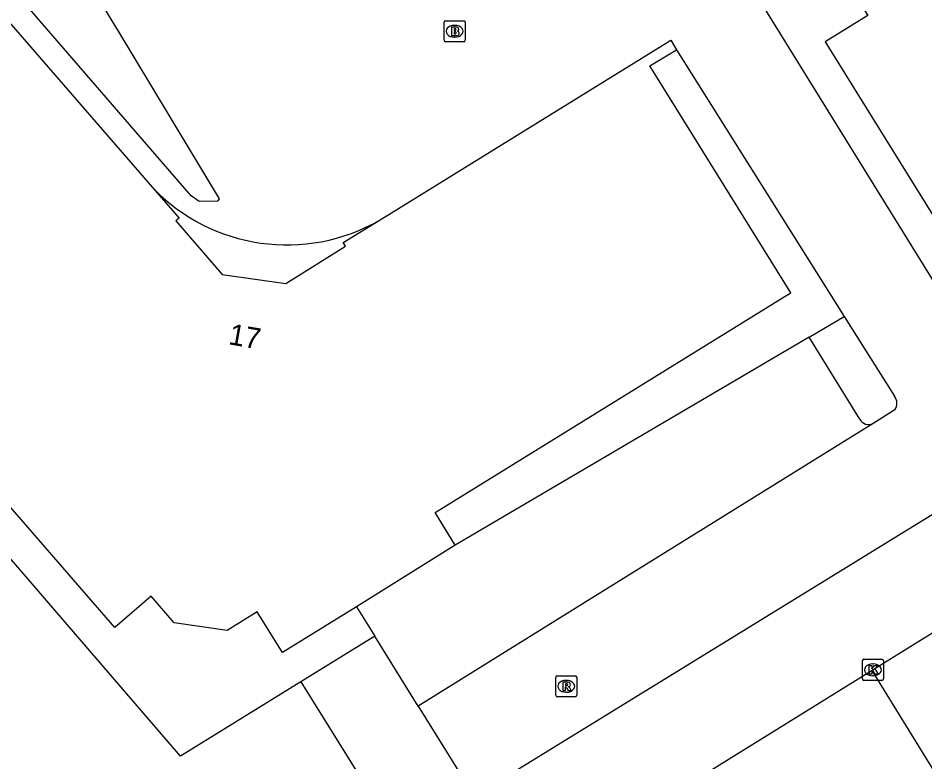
# Model space of a CAD drawing. Extents: x 160304 to 160954, y 383686 to 384161.
# Drawn here: x 160674.85 to 160717.85, y 384030.21 to 384065.5 of the extents above; entities that cross this region are included whole.
import ezdxf

# ---------------------------------------------------------------- set-up
doc = ezdxf.new("R2010")
doc.units = 0
for name, color, linetype in [('IMGEO_Brandkraan', 7, 'Continuous'), ('IMGEO_Kolk', 7, 'Continuous'), ('IMGEO_Pand', 7, 'Continuous'), ('IMGEO_Pand_nummerreeks', 7, 'Continuous'), ('IMGEO_Parkeervlak_open', 7, 'Continuous'), ('IMGEO_Rijbaan_lokaal_open', 7, 'Continuous'), ('IMGEO_Rioolput', 7, 'Continuous'), ('IMGEO_Voetpad_open', 7, 'Continuous')]:
    doc.layers.add(name, color=color, linetype=linetype)

msp = doc.modelspace()

# ---------------------------------------------------------------- linework, layer by layer
at = {"layer": 'IMGEO_Brandkraan'}
for p, q in [((160695.05, 384064.448), (160695.05, 384065.3)), ((160695.125, 384065.374), (160695.977, 384065.374)), ((160696.051, 384065.3), (160696.051, 384064.448)), ((160695.538, 384065.154), (160695.563, 384065.154)), ((160695.561, 384064.594), (160695.536, 384064.594)), ((160695.977, 384064.374), (160695.125, 384064.374))]:
    msp.add_line(p, q, dxfattribs=at)
for points in [[(160695.05, 384064.448), (160695.05, 384065.3)], [(160695.125, 384065.374), (160695.977, 384065.374)], [(160696.051, 384065.3), (160696.051, 384064.448)], [(160695.398, 384065.074), (160695.398, 384064.674), (160695.611, 384064.674)], [(160695.629, 384065.074), (160695.398, 384065.074)], [(160695.577, 384064.993), (160695.523, 384064.993), (160695.523, 384064.917)], [(160695.523, 384064.917), (160695.576, 384064.917)], [(160695.585, 384064.841), (160695.523, 384064.841), (160695.523, 384064.76)], [(160695.523, 384064.76), (160695.585, 384064.76)], [(160695.977, 384064.374), (160695.125, 384064.374)]]:
    msp.add_lwpolyline(points, dxfattribs=at)
for centre, radius, start, end in [((160695.127, 384065.298), 0.0765, 91.552, 178.448), ((160695.127, 384065.298), 0.0765, 91.552, 178.448), ((160695.975, 384065.298), 0.0765, 1.552, 88.448), ((160695.975, 384065.298), 0.0765, 1.552, 88.448), ((160695.578, 384064.955), 0.0379, 267.8285, 90.9355), ((160695.633, 384064.929), 0.145, 59.4692, 91.5367), ((160695.658, 384064.976), 0.0922, 285.5137, 58.1501), ((160695.663, 384064.784), 0.105, 301.3115, 78.989), ((160695.127, 384064.45), 0.0765, 181.552, 268.448), ((160695.127, 384064.45), 0.0765, 181.552, 268.448), ((160695.586, 384064.8), 0.0404, 269.8759, 90.5077), ((160695.617, 384064.925), 0.251, 268.6676, 293.5347), ((160695.975, 384064.45), 0.0765, 271.552, 358.448), ((160695.975, 384064.45), 0.0765, 271.552, 358.448)]:
    msp.add_arc(centre, radius, start, end, dxfattribs=at)
for centre, major_axis, ratio, start_param, end_param in [((160695.537, 384064.874), (-0.387, 0.002), 0.722429, 4.712389, 7.853982), ((160695.562, 384064.874), (-0.39, 0.002), 0.717154, 1.570796, 4.712389)]:
    msp.add_ellipse(centre, major_axis=major_axis, ratio=ratio, start_param=start_param, end_param=end_param, dxfattribs=at)
at = {"layer": 'IMGEO_Kolk'}
for p, q in [((160714.884, 384034.152), (160714.884, 384035.004)), ((160714.959, 384035.078), (160715.811, 384035.078)), ((160715.372, 384034.858), (160715.397, 384034.858)), ((160715.885, 384035.004), (160715.885, 384034.152)), ((160715.811, 384034.078), (160714.959, 384034.078)), ((160715.395, 384034.298), (160715.37, 384034.298))]:
    msp.add_line(p, q, dxfattribs=at)
for points in [[(160714.884, 384034.152), (160714.884, 384035.004)], [(160714.959, 384035.078), (160715.811, 384035.078)], [(160715.205, 384034.778), (160715.328, 384034.778), (160715.328, 384034.627), (160715.458, 384034.778), (160715.622, 384034.778), (160715.476, 384034.627), (160715.629, 384034.378), (160715.477, 384034.378), (160715.392, 384034.542), (160715.328, 384034.475), (160715.328, 384034.378), (160715.205, 384034.378), (160715.205, 384034.778)], [(160715.885, 384035.004), (160715.885, 384034.152)], [(160715.811, 384034.078), (160714.959, 384034.078)]]:
    msp.add_lwpolyline(points, dxfattribs=at)
for centre, start, end in [((160714.961, 384035.002), 91.552, 178.448), ((160714.961, 384035.002), 91.552, 178.448), ((160715.809, 384035.002), 1.552, 88.448), ((160715.809, 384035.002), 1.552, 88.448), ((160714.961, 384034.154), 181.552, 268.448), ((160714.961, 384034.154), 181.552, 268.448), ((160715.809, 384034.154), 271.552, 358.448), ((160715.809, 384034.154), 271.552, 358.448)]:
    msp.add_arc(centre, 0.0765, start, end, dxfattribs=at)
for centre, major_axis, ratio, start_param, end_param in [((160715.371, 384034.578), (-0.387, 0.002), 0.722429, 4.712389, 7.853982), ((160715.396, 384034.578), (-0.39, 0.002), 0.717154, 1.570796, 4.712389)]:
    msp.add_ellipse(centre, major_axis=major_axis, ratio=ratio, start_param=start_param, end_param=end_param, dxfattribs=at)
at = {"layer": 'IMGEO_Pand'}
for points in [[(160660.687, 384076.023), (160662.817, 384077.869), (160661.847, 384078.987), (160662.262, 384079.347), (160681.221, 384057.468)], [(160718.989, 384072.622), (160720.124, 384070.796), (160714.211, 384067.125), (160715.145, 384065.622), (160713.123, 384064.367), (160726.004, 384043.621), (160733.056, 384047.999)], [(160690.89, 384037.575), (160687.392, 384035.398), (160686.188, 384037.334), (160684.762, 384036.447), (160682.256, 384036.811), (160681.157, 384038.082), (160679.439, 384036.595), (160651.874, 384068.387)], [(160692.014, 384055.93), (160705.803, 384064.45), (160706.073, 384064.001)], [(160695.582, 384040.495), (160694.629, 384042.042), (160711.18, 384052.269), (160711.492, 384052.462), (160704.809, 384063.238), (160706.073, 384064.001)], [(160681.221, 384057.468), (160682.482, 384056.013), (160682.324, 384055.876), (160684.524, 384053.338), (160687.54, 384052.902), (160690.381, 384054.674), (160690.27, 384054.852), (160692.014, 384055.93)], [(160695.582, 384040.495), (160690.89, 384037.575)]]:
    msp.add_lwpolyline(points, dxfattribs=at)
at = {"layer": 'IMGEO_Parkeervlak_open'}
for points in [[(160693.825, 384032.859), (160691.762, 384036.175)], [(160715.343, 384034.554), (160706.863, 384029.281)]]:
    msp.add_lwpolyline(points, dxfattribs=at)
at = {"layer": 'IMGEO_Rijbaan_lokaal_open'}
for points in [[(160673.275, 384075.21), (160679.603, 384064.881), (160684.384, 384056.924), (160684.307, 384056.808), (160683.435, 384056.801), (160683.051, 384057.063), (160670.643, 384071.435), (160662.613, 384081.053), (160661.415, 384079.839), (160660.141, 384080.752), (160660.534, 384084.173), (160660.963, 384085.478)], [(160723.208, 384045.029), (160706.486, 384072.081), (160707.989, 384073.011)], [(160706.073, 384064.001), (160714.021, 384051.35)], [(160714.021, 384051.35), (160716.402, 384047.56)], [(160716.431, 384046.914), (160715.395, 384046.269)], [(160715.395, 384046.269), (160701.722, 384037.769), (160693.825, 384032.859)], [(160696.482, 384028.586), (160701.692, 384031.792), (160723.208, 384045.029)], [(160688.256, 384034.009), (160682.556, 384030.486), (160672.68, 384041.948)], [(160720.51, 384037.766), (160715.343, 384034.554)], [(160724.118, 384020.31), (160715.343, 384034.554)], [(160688.256, 384034.009), (160692.299, 384027.507)], [(160693.825, 384032.859), (160695.799, 384029.684)]]:
    msp.add_lwpolyline(points, dxfattribs=at)
for centre, radius, start, end in [((160687.592, 384063.537), 8.799, 223.6096, 300.1703), ((160715.974, 384047.217), 0.548, 326.4399, 38.7009)]:
    msp.add_arc(centre, radius, start, end, dxfattribs=at)
at = {"layer": 'IMGEO_Rioolput'}
for p, q in [((160700.342, 384033.372), (160700.342, 384034.224)), ((160700.417, 384034.298), (160701.269, 384034.298)), ((160700.83, 384034.078), (160700.855, 384034.078)), ((160701.343, 384034.224), (160701.343, 384033.372)), ((160700.853, 384033.518), (160700.828, 384033.518)), ((160701.269, 384033.298), (160700.417, 384033.298))]:
    msp.add_line(p, q, dxfattribs=at)
for points in [[(160700.342, 384033.372), (160700.342, 384034.224)], [(160700.417, 384034.298), (160701.269, 384034.298)], [(160700.931, 384033.996), (160700.679, 384033.998), (160700.679, 384033.598)], [(160700.857, 384033.917), (160700.803, 384033.917), (160700.803, 384033.836)], [(160701.343, 384034.224), (160701.343, 384033.372)], [(160700.679, 384033.598), (160700.803, 384033.598), (160700.803, 384033.76), (160700.814, 384033.76)], [(160700.803, 384033.836), (160700.855, 384033.836)], [(160700.861, 384033.731), (160700.932, 384033.598), (160701.072, 384033.598), (160701.007, 384033.724)], [(160701.269, 384033.298), (160700.417, 384033.298)]]:
    msp.add_lwpolyline(points, dxfattribs=at)
for centre, radius, start, end in [((160700.419, 384034.222), 0.0765, 91.552, 178.448), ((160700.419, 384034.222), 0.0765, 91.552, 178.448), ((160700.863, 384033.821), 0.0964, 77.0061, 93.1865), ((160700.877, 384033.878), 0.0378, 276.6634, 79.6772), ((160700.93, 384033.886), 0.109, 350.3612, 89.416), ((160701.267, 384034.222), 0.0765, 1.552, 88.448), ((160701.267, 384034.222), 0.0765, 1.552, 88.448), ((160700.813, 384033.707), 0.0533, 26.0293, 88.6989), ((160700.839, 384034.025), 0.19, 274.7715, 282.9687), ((160700.928, 384033.886), 0.112, 277.5842, 350.9817), ((160700.912, 384033.671), 0.108, 29.5134, 73.7905), ((160700.419, 384033.374), 0.0765, 181.552, 268.448), ((160700.419, 384033.374), 0.0765, 181.552, 268.448), ((160701.267, 384033.374), 0.0765, 271.552, 358.448), ((160701.267, 384033.374), 0.0765, 271.552, 358.448)]:
    msp.add_arc(centre, radius, start, end, dxfattribs=at)
for centre, major_axis, ratio, start_param, end_param in [((160700.829, 384033.798), (-0.387, 0.002), 0.722429, 4.712389, 7.853982), ((160700.854, 384033.798), (-0.39, 0.002), 0.717154, 1.570796, 4.712389)]:
    msp.add_ellipse(centre, major_axis=major_axis, ratio=ratio, start_param=start_param, end_param=end_param, dxfattribs=at)
at = {"layer": 'IMGEO_Voetpad_open'}
for points in [[(160712.354, 384050.369), (160714.021, 384051.35)], [(160712.354, 384050.369), (160695.582, 384040.495)], [(160714.759, 384046.478), (160712.354, 384050.369)], [(160690.89, 384037.575), (160691.762, 384036.175)], [(160691.762, 384036.175), (160688.256, 384034.009)]]:
    msp.add_lwpolyline(points, dxfattribs=at)
msp.add_arc((160715.179, 384046.683), 0.467, 206.0005, 297.6168, dxfattribs=at)

# ---------------------------------------------------------------- texts
at = {"layer": 'IMGEO_Pand_nummerreeks'}
msp.add_text('17', height=1, rotation=349.9904, dxfattribs=at).set_placement((160684.792, 384050.032))

doc.saveas('drawing.dxf')
